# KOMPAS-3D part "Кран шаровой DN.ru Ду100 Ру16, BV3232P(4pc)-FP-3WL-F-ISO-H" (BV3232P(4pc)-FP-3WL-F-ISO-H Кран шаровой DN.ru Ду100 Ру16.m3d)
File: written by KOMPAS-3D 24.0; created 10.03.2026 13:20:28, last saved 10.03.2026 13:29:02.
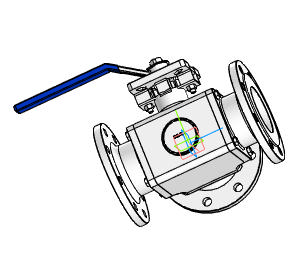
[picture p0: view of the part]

Document properties: Автор: R2D2; Полное имя файла: BV3232P(4pc)-FP-3WL-F-ISO-H Кран шаровой DN.ru Ду100 Ру16.cdw

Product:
- Part/product: Кран шаровой DN.ru Ду100 Ру16  | designation BV3232P(4pc)-FP-3WL-F-ISO-H
    Масса: 58.5
    Раздел спецификации: Прочие изделия
    Форматы листов документа: A2
    Примечание: D160-36363

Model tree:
1. Операция без истории:3

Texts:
  BV3232P(4pc)-FP-3WL-F-ISO-H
